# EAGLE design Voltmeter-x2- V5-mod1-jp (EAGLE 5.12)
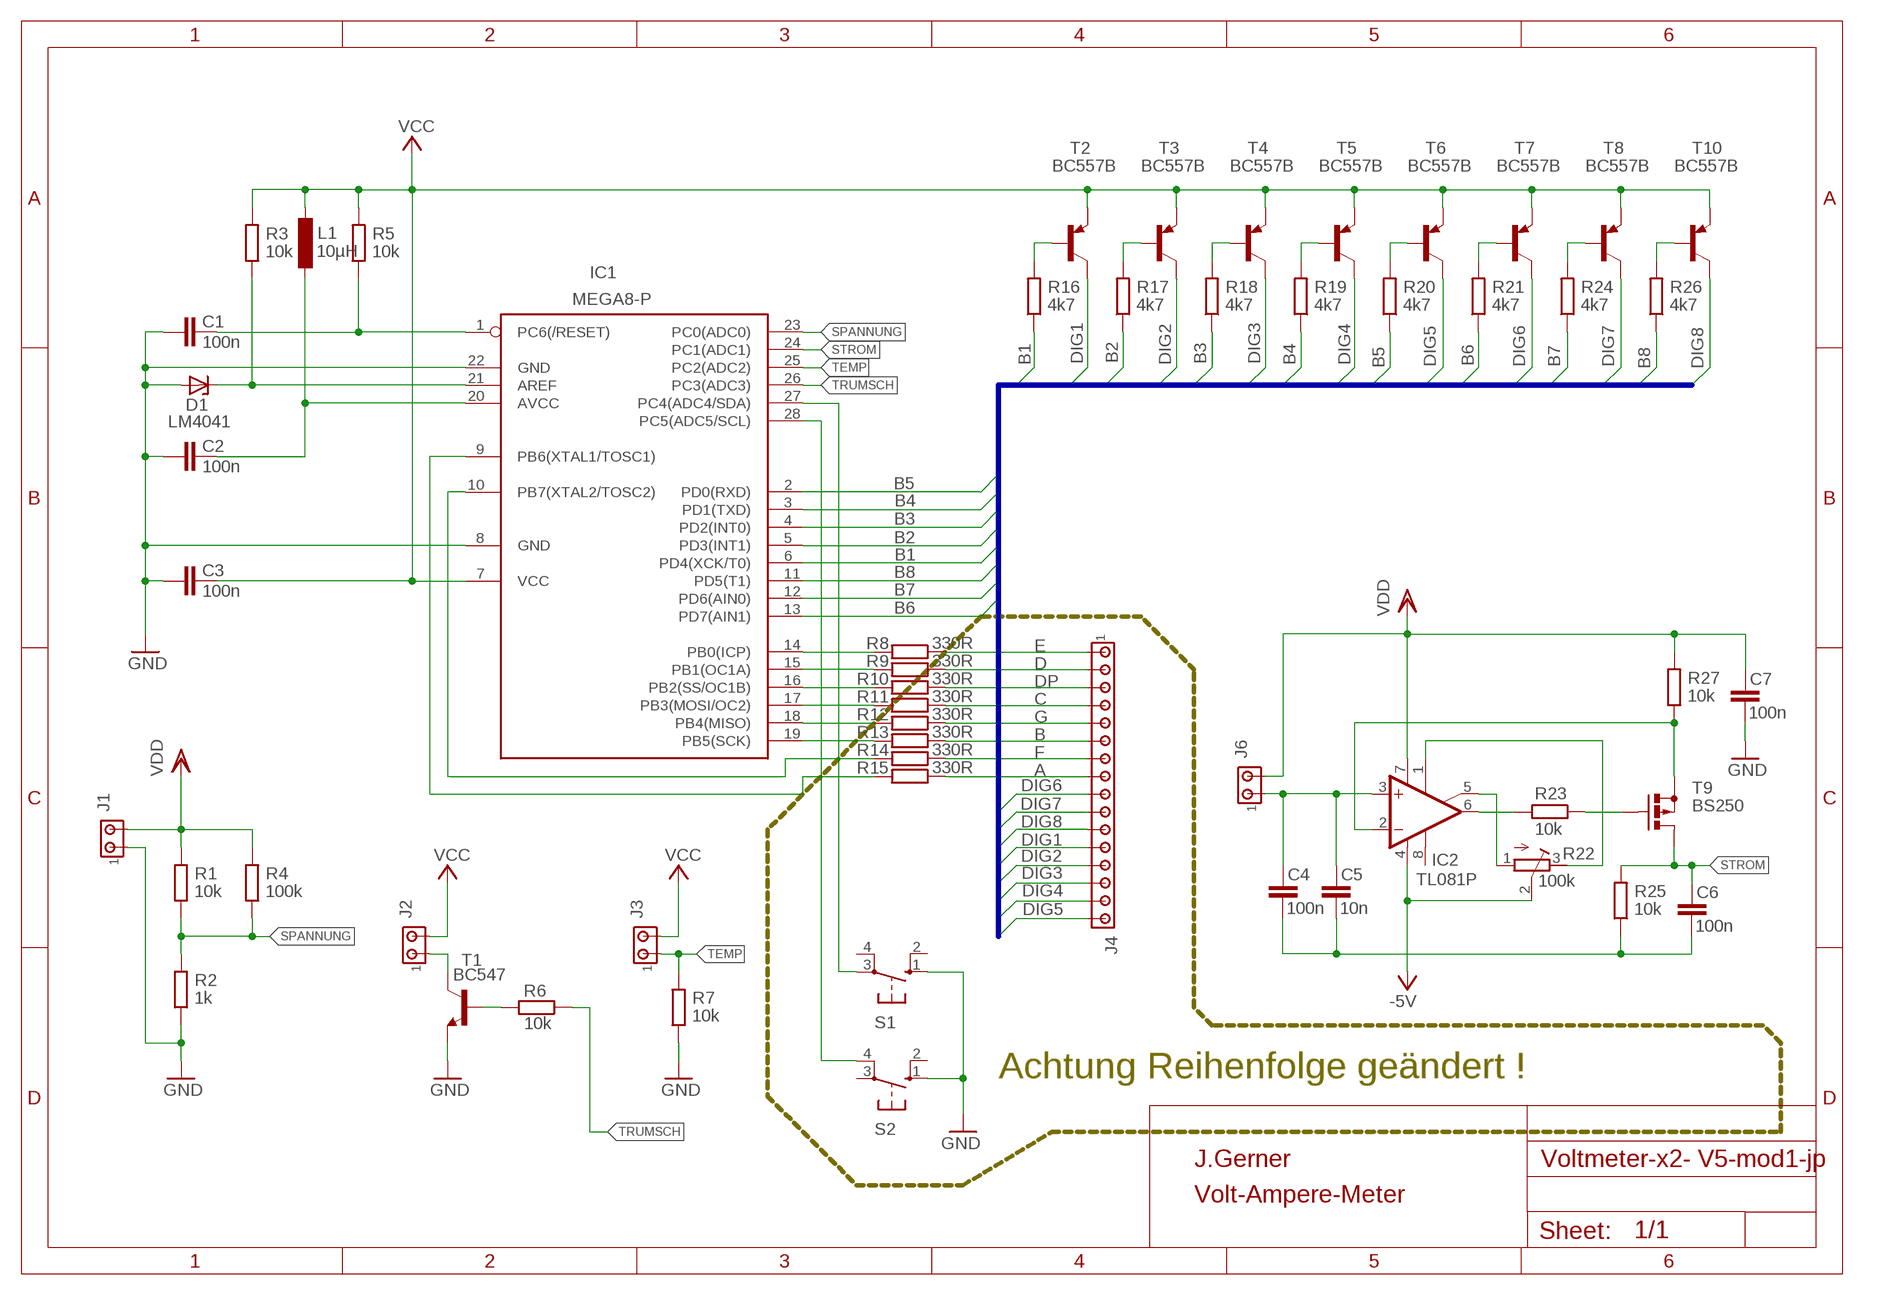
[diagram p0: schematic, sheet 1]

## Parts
C1  100n  C-EUC0805K  [C0805K]
C2  100n  C-EUC0805K  [C0805K]
C3  100n  C-EUC0805K  [C0805K]
C4  100n  C-EUC0805K  [C0805K]
C5  10n  C-EUC0805K  [C0805K]
C6  100n  C-EUC0805K  [C0805K]
C7  100n  C-EUC0805K  [C0805K]
D1  LM4041  1N4728  [DO41Z10]
IC1  MEGA8-P  [DIL28-3]
IC2  TL081P  [DIL08]
J1  MTA02-100  [10X02MTA]
J2  MTA02-100  [10X02MTA]
J3  MTA02-100  [10X02MTA]
J4  MTA16-156  [1X16MTA]
J6  MTA02-100  [10X02MTA]
L1  10µH  L-EU0207/10  [0207/10]
R1  10k  R-EU_0207/10  [0207/10]
R2  1k  R-EU_0204/7  [0204/7]
R3  10k  R-EU_0207/10  [0207/10]
R4  100k  R-EU_0207/10  [0207/10]
R5  10k  R-EU_0204/7  [0204/7]
R6  10k  R-EU_0207/12  [0207/12]
R7  10k  R-EU_0204/7  [0204/7]
R8  330R  R-EU_0204/2V  [0204V]
R9  330R  R-EU_0204/2V  [0204V]
R10  330R  R-EU_0204/2V  [0204V]
R11  330R  R-EU_0204/2V  [0204V]
R12  330R  R-EU_0204/2V  [0204V]
R13  330R  R-EU_0204/2V  [0204V]
R14  330R  R-EU_0204/2V  [0204V]
R15  330R  R-EU_0204/2V  [0204V]
R16  4k7  R-EU_0204/2V  [0204V]
R17  4k7  R-EU_0204/2V  [0204V]
R18  4k7  R-EU_0204/2V  [0204V]
R19  4k7  R-EU_0204/2V  [0204V]
R20  4k7  R-EU_0204/2V  [0204V]
R21  4k7  R-EU_0204/2V  [0204V]
R22  100k  R-TRIMM3296Y  [RTRIM3296Y]
R23  10k  R-EU_0204/2V  [0204V]
R24  4k7  R-EU_0204/2V  [0204V]
R25  10k  R-EU_0204/7  [0204/7]
R26  4k7  R-EU_0204/2V  [0204V]
R27  10k  R-EU_0204/2V  [0204V]
S1  10-XX  [B3F-10XX]
S2  10-XX  [B3F-10XX]
T1  BC547  BC547B-NPN-TO92-CBE  [TO92-CBE]
T2  BC557B  [TO92-EBC]
T3  BC557B  [TO92-EBC]
T4  BC557B  [TO92-EBC]
T5  BC557B  [TO92-EBC]
T6  BC557B  [TO92-EBC]
T7  BC557B  [TO92-EBC]
T8  BC557B  [TO92-EBC]
T9  BS250  [SOT54E]
T10  BC557B  [TO92-EBC]

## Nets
-5V: IC2.4(V-) R22.2(S)
A: J4.8 R15.1
B: J4.6 R13.1
B1: IC1.6(PD4(XCK/T0)) R16.1
B2: IC1.5(PD3(INT1)) R17.1
B3: IC1.4(PD2(INT0)) R18.1
B4: IC1.3(PD1(TXD)) R19.1
B5: IC1.2(PD0(RXD)) R20.1
B6: IC1.13(PD7(AIN1)) R21.1
B7: IC1.12(PD6(AIN0)) R24.1
B8: IC1.11(PD5(T1)) R26.1
C: J4.4 R11.1
D: J4.2 R9.1
DIG1: J4.12 T2.C
DIG2: J4.13 T3.C
DIG3: J4.14 T4.C
DIG4: J4.15 T5.C
DIG5: J4.16 T6.C
DIG6: J4.9 T7.C
DIG7: J4.10 T8.C
DIG8: J4.11 T10.C
DP: J4.3 R10.1
E: J4.1 R8.1
F: J4.7 R14.1
G: J4.5 R12.1
GND: C1.2 C2.2 C3.2 C7.2 D1.A IC1.8(GND) IC1.22(GND) J1.1 R2.1 R7.1 S1.1(S) S2.1(S) T1.E
N$1: C1.1 IC1.1(PC6(/RESET)) R5.1
N$2: IC1.10(PB7(XTAL2/TOSC2)) R14.2
N$3: D1.C IC1.21(AREF) R3.1
N$4: C2.1 IC1.20(AVCC) L1.2
N$5: IC1.9(PB6(XTAL1/TOSC1)) R15.2
N$6: R16.2 T2.B
N$7: R17.2 T3.B
N$8: IC1.14(PB0(ICP)) R8.2
N$9: R18.2 T4.B
N$10: IC1.15(PB1(OC1A)) R9.2
N$11: R19.2 T5.B
N$12: IC1.16(PB2(SS/OC1B)) R10.2
N$13: R20.2 T6.B
N$14: IC1.17(PB3(MOSI/OC2)) R11.2
N$15: R21.2 T7.B
N$16: IC1.18(PB4(MISO)) R12.2
N$17: IC1.19(PB5(SCK)) R13.2
N$18: R24.2 T8.B
N$19: IC2.6(OUT) R23.2
N$20: R26.2 T10.B
N$21: R23.1 T9.G
N$22: IC2.5(ON2) R22.1(A)
N$23: IC2.1(ON1) R22.3(E)
N$24: IC2.2(-IN) R27.1 T9.S
N$25: C4.1 C5.1 IC2.3(+IN) J6.1
N$26: C4.2 C5.2 C6.2 R25.1
N$27: J2.1 T1.C
N$28: R6.2 T1.B
N$30: IC1.28(PC5(ADC5/SCL)) S2.4(P1)
N$31: IC1.27(PC4(ADC4/SDA)) S1.3(P)
SPANNUNG: IC1.23(PC0(ADC0)) R1.1 R2.2 R4.1
STROM: C6.1 IC1.24(PC1(ADC1)) R25.2 T9.D
TEMP: IC1.25(PC2(ADC2)) J3.1 R7.2
TRUMSCH: IC1.26(PC3(ADC3)) R6.1
VCC: C3.1 IC1.7(VCC) J2.2 J3.2 L1.1 R3.2 R5.2 T2.E T3.E T4.E T5.E T6.E T7.E T8.E T10.E
VDD: C7.1 IC2.7(V+) J1.2 J6.2 R1.2 R4.2 R27.2
Unconnected: IC2.8(OPT) S1.2(S1) S1.4(P1) S2.2(S1) S2.3(P)

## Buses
B[1..8],DIG[1..8]

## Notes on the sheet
- Achtung Reihenfolge geändert !
- J.Gerner
- Volt-Ampere-Meter

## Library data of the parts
C1-C7 = rcl:C-EU: CAPACITOR, European symbol
D1 = diode:1N4728: Z DIODE
IC1 = atmel:MEGA8-P: MICROCONTROLLER 8 Kbytes FLASH, 1 kbytes SRAM, 512 bytes EEPROM, USART, 4-channel 10 bit ADC, 2-channel 8 bit ADC Pin compatible with Atmega48, ATMega88, ATMega168 Source: avr.lbr; OC_FARNELL: unknown; OC_NEWARK: unknown
IC2 = burr-brown-JP:TL081: OP AMP
J1-J3 J6 = con-amp:MTA02-100: AMP connector; OC_FARNELL: unknown; OC_NEWARK: unknown
J4 = con-amp:MTA16-156: AMP connector; OC_FARNELL: unknown; OC_NEWARK: unknown
L1 = rcl:L-EU: INDUCTOR, European symbol
R1-R21 R23-R27 = rcl:R-EU_: RESISTOR, European symbol
R22 = rcl:R-TRIMM: Trimm resistor
S1 S2 = switch-omron:10-XX: OMRON SWITCH; MPN: B3F-1000; OC_FARNELL: 176432; OC_NEWARK: 36M3542
T1 = transistor:*-NPN-: NPN Transistror BF959 corrected 2008.03.06
T2-T8 T10 = transistor-pnp:BC557*: PNP Transistror
T9 = transistor-small-signal:BS250: P-CHANNEL MOS FET

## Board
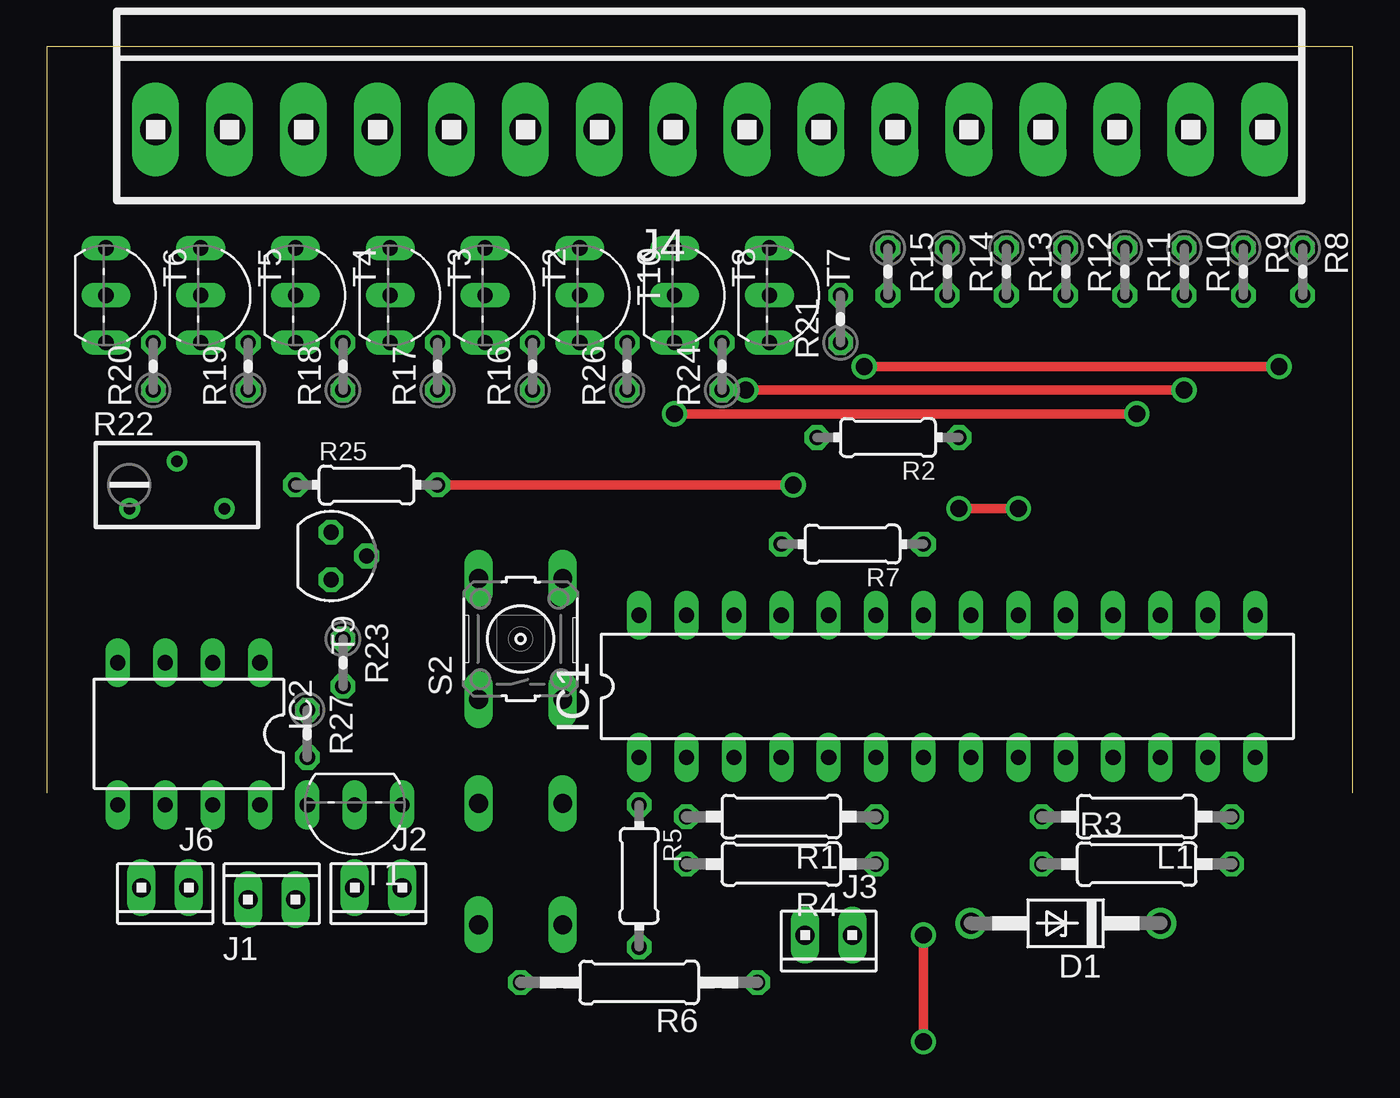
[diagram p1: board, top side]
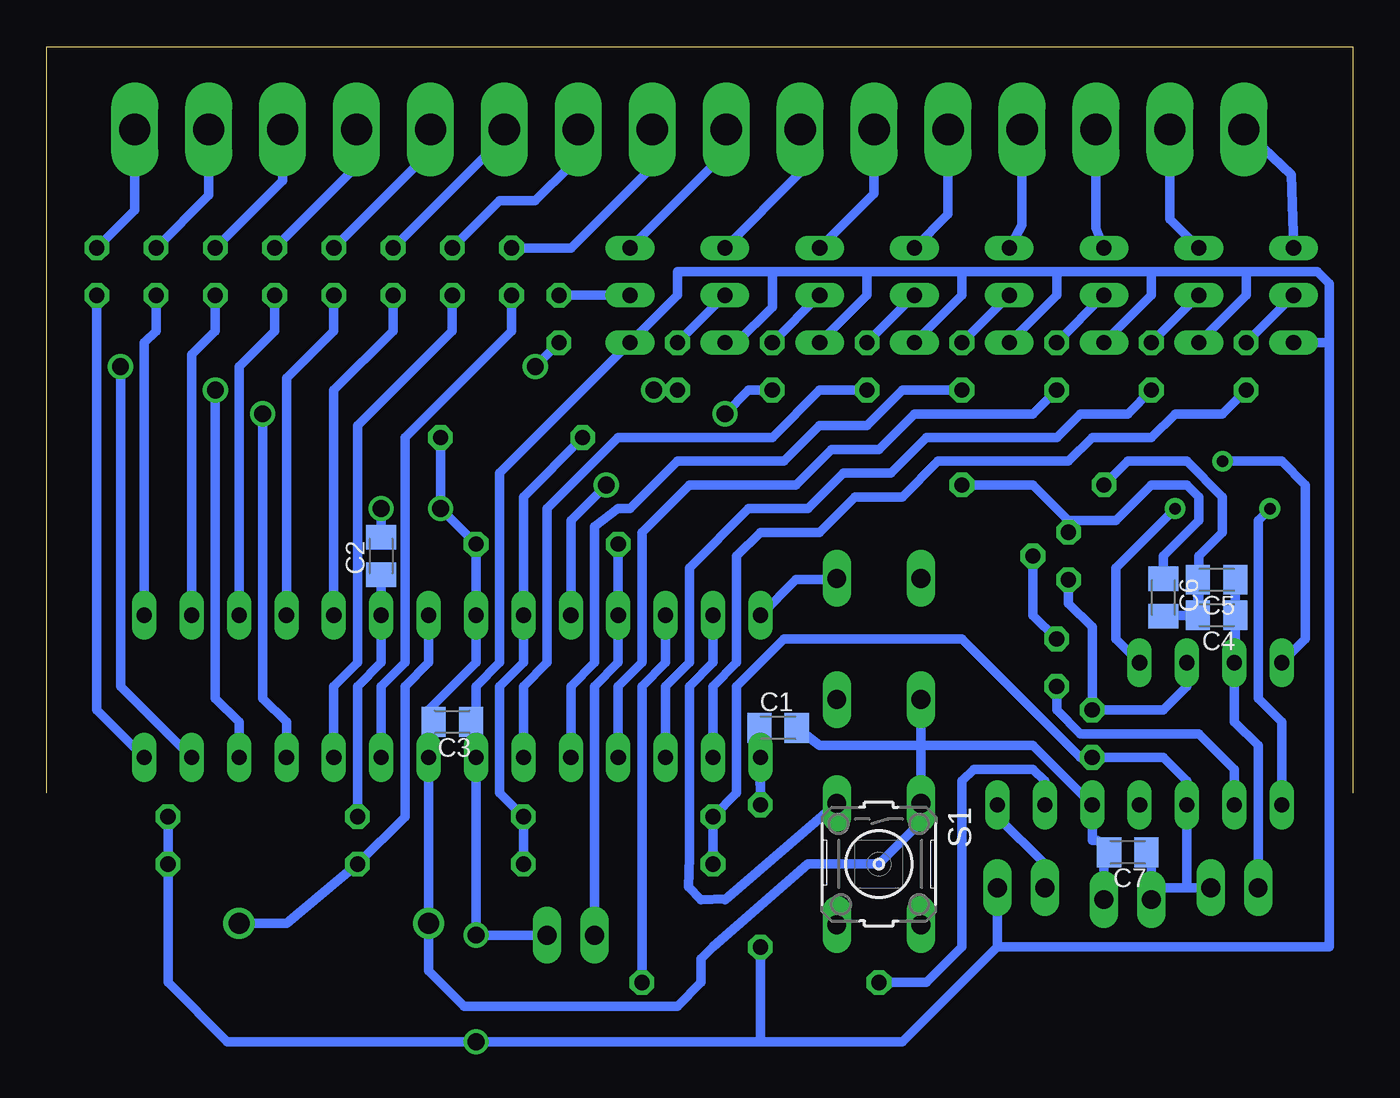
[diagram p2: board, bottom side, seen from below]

Size 70 x 40 mm. Coordinates in mm from the lower left corner, seen from the top.
Outline: 70,0 70,40 0,40 0,0
Copper layers (1*16): Top 0.035mm / dielectric 1.5mm / Bottom 0.035mm
Design rules "default *": minimum track width 20mil, minimum drill 24mil, track to track 8mil, track to pad 8mil, pad to pad 8mil, via to via 8mil, smd to smd 8mil, copper to edge 40mil, drill to drill 8mil, minimum pad ring 10mil, minimum via ring 8mil, stop-mask expansion 4mil, vias tented up to drill 0mil, thermal gap 10mil

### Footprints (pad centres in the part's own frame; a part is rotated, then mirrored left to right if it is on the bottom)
C0805K = smd 1.3 x 1.6: 1 -1,0; 2 1,0
DO41Z10 = drill 1.118 round: A 5.08,0; C -5.08,0
DIL28-3 = drill 0.813 long: 1 -16.51,-3.81; 2 -13.97,-3.81; 3 -11.43,-3.81; 4 -8.89,-3.81; 5 -6.35,-3.81; 6 -3.81,-3.81; 7 -1.27,-3.81; 8 1.27,-3.81; 9 3.81,-3.81; 10 6.35,-3.81; 11 8.89,-3.81; 12 11.43,-3.81; 13 13.97,-3.81; 14 16.51,-3.81; 15 16.51,3.81; 16 13.97,3.81; 17 11.43,3.81; 18 8.89,3.81; 19 6.35,3.81; 20 3.81,3.81; 21 1.27,3.81; 22 -1.27,3.81; 23 -3.81,3.81; 24 -6.35,3.81; 25 -8.89,3.81; 26 -11.43,3.81; 27 -13.97,3.81; 28 -16.51,3.81
DIL08 = drill 0.813 long: 1 -3.81,-3.81; 2 -1.27,-3.81; 3 1.27,-3.81; 4 3.81,-3.81; 5 3.81,3.81; 6 1.27,3.81; 7 -1.27,3.81; 8 -3.81,3.81
10X02MTA = drill 1.016 long: 1 1.27,0; 2 -1.27,0
1X16MTA = drill 1.676 long: 1 29.718,0; 2 25.756,0; 3 21.793,0; 4 17.831,0; 5 13.868,0; 6 9.906,0; 7 5.944,0; 8 1.981,0; 9 -1.981,0; 10 -5.944,0; 11 -9.906,0; 12 -13.868,0; 13 -17.831,0; 14 -21.793,0; 15 -25.756,0; 16 -29.718,0
0207/10 = drill 0.813 octagon: 1 -5.08,0; 2 5.08,0
0204/7 = drill 0.813 octagon: 1 -3.81,0; 2 3.81,0
0207/12 = drill 0.813 octagon: 1 -6.35,0; 2 6.35,0
0204V = drill 0.813 octagon: 1 -1.27,0; 2 1.27,0
RTRIM3296Y = drill 0.61 round: 1 1.27,-2.54; 2 -1.27,0; 3 1.27,2.54
B3F-10XX = drill 1.016 long: 1 -3.251,2.261; 2 3.251,2.261; 3 -3.251,-2.261; 4 3.251,-2.261
TO92-CBE = drill 0.813 long: B 0,0; C -2.54,0; E 2.54,0
TO92-EBC = drill 0.813 long: B 0,-1.27; C -2.54,-1.27; E 2.54,-1.27
SOT54E = drill 0.813 octagon: D -1.27,0; G 0,1.905; S 1.27,0

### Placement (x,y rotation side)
C1  30.8,3.49 0 bottom
C2  52.07,12.7 90 bottom
C3  48.26,3.81 180 bottom
C4  7.3,9.53 180 bottom
C5  7.3,11.43 180 bottom
C6  10.16,10.48 270 bottom
C7  12.06,-3.17 180 bottom  (outside the outline)
D1  54.61,-6.99 180 top  (outside the outline)
IC1  48.26,5.71 0 top
IC2  7.62,3.17 180 top
J1  12.06,-5.71 0 top  (outside the outline)
J2  17.78,-5.08 180 top  (outside the outline)
J3  41.91,-7.62 180 top  (outside the outline)
J4  35.56,35.56 0 top
J6  6.35,-5.08 180 top  (outside the outline)
L1  58.42,-1.27 180 top
R1  39.37,-1.27 180 top
R2  45.09,19.05 180 top
R3  58.42,-3.81 0 top  (outside the outline)
R4  39.37,-3.81 180 top  (outside the outline)
R5  31.75,-4.45 270 top
R6  31.75,-10.16 180 top  (outside the outline)
R7  43.18,13.34 180 top
R8  67.31,27.94 270 top
R9  64.14,27.94 270 top
R10  60.96,27.94 270 top
R11  57.78,27.94 270 top
R12  54.61,27.94 270 top
R13  51.44,27.94 270 top
R14  48.26,27.94 270 top
R15  45.09,27.94 270 top
R16  26.04,22.86 90 top
R17  20.95,22.86 90 top
R18  15.88,22.86 90 top
R19  10.79,22.86 90 top
R20  5.71,22.86 90 top
R21  42.55,25.4 90 top
R22  6.99,16.51 270 top
R23  15.88,6.99 270 top
R24  36.2,22.86 90 top
R25  17.14,16.51 0 top
R26  31.11,22.86 90 top
R27  13.97,3.17 270 top
S1  25.4,-3.81 270 bottom
S2  25.4,8.26 90 top
T1  16.51,-0.64 180 top
T2  24.77,26.67 270 top
T3  19.68,26.67 270 top
T4  14.61,26.67 270 top
T5  9.53,26.67 270 top
T6  4.45,26.67 270 top
T7  40.01,26.67 270 top
T8  34.92,26.67 270 top
T9  15.24,12.7 270 top
T10  29.84,26.67 270 top

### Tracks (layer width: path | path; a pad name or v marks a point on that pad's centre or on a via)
-5V
  Bottom 0.508: R22.2 3.81,17.78 2.54,16.51 2.54,8.26 IC2.4
A
  Bottom 0.508: J4.8 37.54,33.58 41.91,29.21 R15.1
B
  Bottom 0.508: J4.6 45.47,35.18 R13.1
B1
  Bottom 0.508: IC1.6 44.45,5.71 43.18,6.99 43.18,15.24 39.37,19.05 31.11,19.05 28.57,21.59 R16.1
B2
  Bottom 0.508: IC1.5 41.91,5.71 40.64,6.99 40.64,14.29 39.37,15.24 38.73,15.24 36.2,17.78 30.48,17.78 28.57,19.68 26.04,19.68 24.13,21.59 R17.1
B3
  Bottom 0.508: IC1.4 39.37,5.71 38.1,6.99 38.1,13.97 35.56,16.51 29.84,16.51 27.94,18.41 25.4,18.41 23.5,20.32 17.14,20.32 R18.1
B4
  Bottom 0.508: IC1.3 36.83,5.71 35.56,6.99 35.56,12.06 32.38,15.24 29.21,15.24 27.3,17.14 24.77,17.14 22.86,19.05 15.88,19.05 14.61,20.32 12.06,20.32 R19.1
B5
  Bottom 0.508: IC1.2 34.29,5.71 33.02,6.99 33.02,12.7 31.75,13.97 28.57,13.97 26.67,15.88 24.13,15.88 22.23,17.78 15.24,17.78 13.97,19.05 10.79,19.05 9.53,20.32 6.99,20.32 R20.1
B6  (via drill 0.9 pad 0.61)
  Top 0.508: v66.04,22.86 v43.81,22.86
  Bottom 0.508: v43.81,22.86 R21.1 | v66.04,22.86 66.04,5.71 IC1.13
B7  (via drill 0.9 pad 0.61)
  Top 0.508: v37.47,21.59 v60.96,21.59
  Bottom 0.508: IC1.12 59.69,3.81 60.96,5.08 v60.96,21.59 | R24.1 v37.47,21.59
B8  (via drill 0.9 pad 0.61)
  Top 0.508: v33.66,20.32 v58.42,20.32
  Bottom 0.508: IC1.11 57.15,3.81 58.42,5.08 v58.42,20.32 | R26.1 32.38,21.59 v33.66,20.32
C
  Bottom 0.508: J4.4 53.39,33.6 R11.1
D
  Bottom 0.508: J4.2 61.32,32.03 R9.1
DIG1
  Bottom 0.508: J4.12 21.69,31.01 T2.C
DIG2
  Bottom 0.508: J4.13 17.73,30.43 T3.C
DIG3
  Bottom 0.508: J4.14 13.77,30.28 T4.C
DIG4
  Bottom 0.508: J4.15 9.8,30.76 T5.C
DIG5
  Bottom 0.508: J4.16 3.3,33.15 T6.C
DIG6
  Bottom 0.508: J4.9 33.58,34.37 T7.C
DIG7
  Bottom 0.508: J4.10 29.62,33.25 T8.C
DIG8
  Bottom 0.508: J4.11 25.65,32.13 T10.C
DP
  Bottom 0.508: J4.3 57.35,32.82 R10.1
E
  Bottom 0.508: J4.1 65.28,31.24 R8.1
F
  Bottom 0.508: J4.7 41.91,35.56 41.91,33.66 43.81,31.75 45.72,31.75 R14.1
G
  Bottom 0.508: J4.5 49.43,34.39 R12.1
GND  (via drill 0.9 pad 0.61)
  Top 0.508: v48.9,15.24 v52.07,15.24
  Bottom 0.508: 49.53,3.81 IC1.8 D1.A 49.53,-9.53 47.62,-11.43 36.2,-11.43 34.92,-10.16 34.92,-8.89 34.29,-8.26 29.21,-3.81 25.4,-3.81 23.5,-1.91 23.5,-0.84 S1.1 23.14,2.54 | R2.1 v48.9,15.24 R7.1 IC1.22 46.99,6.99 49.53,4.45 49.53,3.81 | 49.53,3.81 C3.2 | J1.1 13.34,-3.44 C7.2 13.7,-2.54 13.97,-2.54 T1.E 17.14,2.54 23.14,2.54 | 23.14,2.54 S2.1 | v52.07,15.24 C2.2 | C1.2 28.57,2.54 23.14,2.54
N$1
  Bottom 0.508: C1.1 R5.1 IC1.1
N$2
  Bottom 0.508: R14.2 48.26,24.77 53.34,19.68 53.34,6.99 54.61,5.71 IC1.10
N$3
  Bottom 0.508: IC1.21 49.53,6.99 50.8,5.71 50.8,-1.27 R3.1 57.15,-6.99 D1.C
N$4
  Bottom 0.508: L1.2 53.34,5.71 52.07,6.99 IC1.20 C2.1
N$5
  Bottom 0.508: R15.2 45.09,24.77 50.8,19.05 50.8,6.99 52.07,5.71 IC1.9
N$6
  Bottom 0.508: R16.2 T2.B
N$7
  Bottom 0.508: R17.2 T3.B
N$8
  Bottom 0.508: IC1.14 67.31,4.45 R8.2
N$9
  Bottom 0.508: R18.2 T4.B
N$10
  Bottom 0.508: IC1.15 64.77,24.13 64.14,24.77 R9.2
N$11
  Bottom 0.508: R19.2 T5.B
N$12
  Bottom 0.508: IC1.16 62.23,23.5 60.96,24.77 R10.2
N$13
  Bottom 0.508: R20.2 T6.B
N$14
  Bottom 0.508: IC1.17 59.69,22.86 57.78,24.77 R11.2
N$15
  Bottom 0.508: T7.B R21.2
N$16
  Bottom 0.508: IC1.18 57.15,22.23 54.61,24.77 R12.2
N$17
  Bottom 0.508: IC1.19 54.61,21.59 51.44,24.77 R13.2
N$18
  Bottom 0.508: R24.2 T8.B
N$19
  Bottom 0.508: IC2.6 6.35,1.27 8.26,3.17 14.61,3.17 15.88,4.45 R23.2
N$20
  Bottom 0.508: R26.2 T10.B
N$21
  Bottom 0.508: R23.1 17.14,9.53 T9.G
N$22
  Bottom 0.508: R22.1 5.08,14.61 5.08,5.08 3.81,3.81 IC2.5
N$23
  Bottom 0.508: IC2.1 12.7,8.26 12.7,12.06 R22.3
N$24
  Bottom 0.508: T9.S 15.24,10.16 13.97,8.89 R27.1 10.16,4.45 8.89,5.71 IC2.2
N$25
  Bottom 0.508: J6.1 5.08,2.54 6.35,3.81 IC2.3 6.3,7.03 C4.1 C5.1
N$26
  Bottom 0.508: C5.2 C4.2 10.11,9.53 C6.2 8.26,9.53 8.26,12.7 6.99,13.97 6.99,15.88 8.89,17.78 12.06,17.78 R25.1
N$27
  Bottom 0.508: T1.C 19.05,-1.27 16.51,-3.81 J2.1
N$28
  Bottom 0.508: R6.2 22.86,-10.16 20.95,-8.26 20.95,0.64 20.32,1.27 17.14,1.27 16.51,0.64 T1.B
N$30
  Bottom 0.508: IC1.28 29.84,11.43 27.94,11.43 arc-60 S2.4
N$31
  Bottom 0.508: S1.3 33.66,-5.71 33.62,-5.68 34.92,-5.71 35.6,-5.04 35.56,-3.45 35.56,5.71 34.29,6.99 IC1.27
SPANNUNG
  Bottom 0.508: R2.2 44.45,15.88 IC1.23 44.45,6.99 45.72,5.71 45.72,0 R1.1 R4.1
STROM  (via drill 0.9 pad 0.61)
  Top 0.508: R25.2 v40.01,16.51
  Bottom 0.508: v40.01,16.51 41.91,14.61 IC1.24 | C6.1 10.16,12.7 8.26,14.61 8.26,15.88 8.89,16.51 10.79,16.51 12.7,14.61 15.24,14.61 | 15.24,14.61 T9.D | R25.2 17.14,16.51 15.24,14.61
TEMP
  Bottom 0.508: R7.2 IC1.25 39.37,6.99 40.64,5.71 J3.1
TRUMSCH
  Bottom 0.508: IC1.26 36.83,6.99 38.1,5.71 R6.1
VCC  (via drill 0.9 pad 0.61)
  Top 0.508: v46.99,-7.62 v46.99,-13.34
  Bottom 0.508: 1.27,24.13 T6.E | 1.27,24.13 1.27,27.3 1.91,27.94 5.71,27.94 | 5.71,27.94 10.79,27.94 | 10.79,27.94 15.88,27.94 | 15.88,27.94 20.95,27.94 | 20.95,27.94 26.04,27.94 | 26.04,27.94 31.11,27.94 | 31.11,27.94 36.2,27.94 36.2,26.67 T7.E 45.72,17.14 45.72,6.99 46.99,5.71 46.99,3.81 | T5.E 5.71,26.67 5.71,27.94 | T4.E 10.79,26.67 10.79,27.94 | T3.E 15.88,26.67 15.88,27.94 | T2.E 20.95,26.67 20.95,27.94 | T10.E 26.04,26.67 26.04,27.94 | T8.E 33.02,24.13 31.11,26.04 31.11,27.94 | 19.05,-8.26 1.27,-8.26 1.27,24.13 | 19.05,-8.26 24.13,-13.34 31.75,-13.34 | R5.2 31.75,-10.79 31.75,-13.34 | 31.75,-13.34 60.33,-13.34 63.5,-10.16 R3.2 L1.1 | 46.99,3.81 IC1.7 v46.99,-7.62 J3.2 | 46.99,3.81 C3.1 | 19.05,-8.26 J2.2
VDD
  Bottom 0.508: R4.2 R1.2 33.02,0 33.02,5.71 30.48,8.26 20.95,8.26 14.61,1.91 R27.2 10.16,1.91 8.89,0.64 IC2.7 8.89,-5.08 | J6.2 8.89,-5.08 | 8.89,-5.08 10.16,-5.08 J1.2 10.79,-3.44 C7.1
